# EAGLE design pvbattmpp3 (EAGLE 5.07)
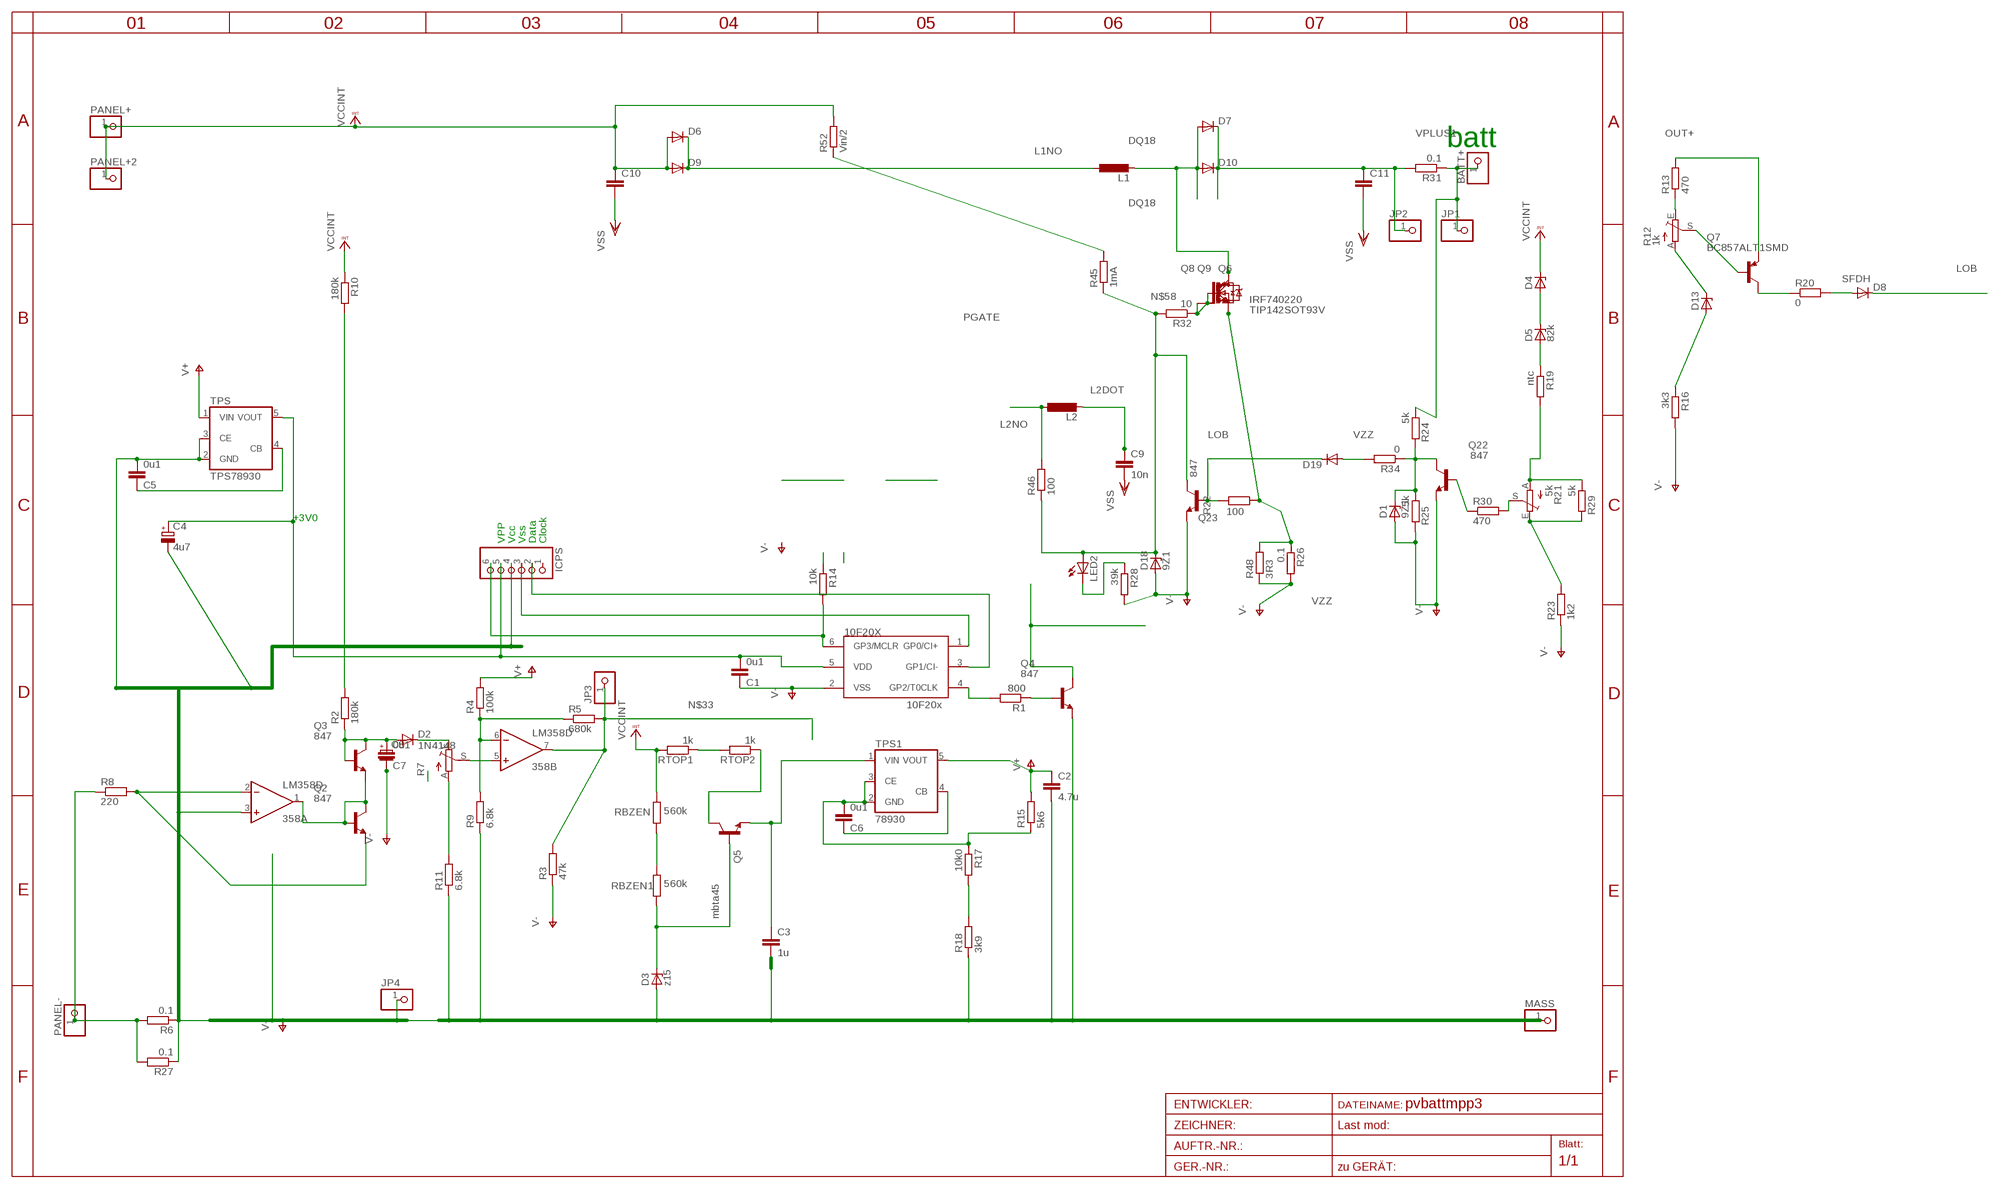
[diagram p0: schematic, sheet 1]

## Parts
10F20X  10F20x  PIC10F204OT  [SOT23-6]
358  LM358D  [SO08]
BATT+  PINHD-1X12MM3  [1X2MM3]
C1  0u1  C-EUC1206  [C1206]
C2  4.7u  C-EUC1206  [C1206]
C3  1u  C-EUC1206  [C1206]
C4  4u7  CPOL-EUSMCA  [SMC_A]
C5  0u1  C-EUC0805  [C0805]
C6  0u1  C-EUC0805  [C0805]
C7  0u1  C-EUC1608  [C1608]
C8  CPOL-EUSMCA  [SMC_A]
C9  10n  C-EUC0805  [C0805]
C10  C-EU075-052X106  [C075-052X106]
C11  C-EU075-052X106  [C075-052X106]
D1  9Z1  ZENER-DIODESOD80C  [SOD80C]
D2  1N4148  DIODE-SOD80C  [SOD80C]
D3  z15  ZENER-DIODESOD80C  [SOD80C]
D4  ZENER-DIODESOD80C  [SOD80C]
D5  82k  ZENER-DIODESOD80C  [SOD80C]
D6  DIODE-SMC  [SMC]
D7  DIODE-SMC  [SMC]
D8  DIODE-MINIMELF  [MINIMELF]
D9  DIODE-SMC  [SMC]
D10  DIODE-SMC  [SMC]
D13  ZENER-DIODESOD80C  [SOD80C]
D18  9Z1  ZENER-DIODESOD80C  [SOD80C]
D19  DIODE-MINIMELF  [MINIMELF]
ICPS  PINHD-1X6  [1X06BOX]
JP1  PINHD-1X11MM6  [1X1MM8]
JP2  PINHD-1X11MM6  [1X1MM8]
JP3  PINHD-1X11MM6  [1X1MM8]
JP4  PINHD-1X11MM6  [1X1MM8]
L1  L-EUOPEN6  [OPEN6_3]
L2  L-EUOPEN6  [OPEN6_3]
LED2  LEDCHIPLED_1206  [CHIPLED_1206]
MASS  PINHD-1X12MM3  [1X2MM3]
PANEL+  PINHD-1X11MM6  [1X1MM8]
PANEL+2  PINHD-1X12MM3  [1X2MM3]
PANEL-  PINHD-1X12MM3  [1X2MM3]
Q2  847  BC847ALT1SMD  [SOT23]
Q3  847  BC847ALT1SMD  [SOT23]
Q4  847  BC847ALT1SMD  [SOT23]
Q5  mbta45  BC847ALT1SMD  [SOT23]
Q6  IRF740220  [TO220BV]
Q7  BC857ALT1SMD  [SOT23-BEC]
Q8  IRG4BC15UD-S  [D2PACK]
Q9  TIP142SOT93V  [SOT93V]
Q22  847  BC847ASMD  [SOT23]
Q23  847  BC847ASMD  [SOT23]
R1  800  R-EU_R0805  [R0805]
R2  180k  R-EU_0207/15  [0207/15]
R3  47k  R-EU_R0805  [R0805]
R4  100k  R-EU_R1206  [R1206]
R5  680k  R-EU_R0805  [R0805]
R6  0.1  R-EU_0207/10  [0207/10]
R7  TRIM_EU-S64W  [S64W]
R8  220  R-EU_R0805  [R0805]
R9  6.8k  R-EU_R1206  [R1206]
R10  180k  R-EU_R1206  [R1206]
R11  6.8k  R-EU_R0805  [R0805]
R12  1k  TRIM_EU-S64W  [S64W]
R13  470  R-EU_R0805  [R0805]
R14  10k  R-EU_R0805  [R0805]
R15  5k6  R-EU_R0805  [R0805]
R16  3k3  R-EU_R0805  [R0805]
R17  10k0  R-EU_R0805  [R0805]
R18  3k9  R-EU_R0805  [R0805]
R19  ntc  R-EU_0204/5  [0204/5]
R20  0  R-EU_R0805  [R0805]
R21  5k  TRIM_EU-S64W  [S64W]
R22  100  R-EU_R1206  [R1206]
R23  1k2  R-EU_R0805  [R0805]
R24  5k  R-EU_R1206  [R1206]
R25  5k  R-EU_R0805  [R0805]
R26  0.1  R-EU_R3216  [R3216]
R27  0.1  R-EU_R3216  [R3216]
R28  39k  R-EU_R0805  [R0805]
R29  5k  R-EU_R0805  [R0805]
R30  470  R-EU_R0805  [R0805]
R31  0.1  R-EU_R1210  [R1210]
R32  10  R-EU_R0805  [R0805]
R34  0  R-EU_R0805  [R0805]
R45  1mA  R-EU_R0805  [R0805]
R46  100  R-EU_R0805  [R0805]
R48  3R3  R-EU_0207/10  [0207/10]
R52  Vin/2  R-EU_R1206  [R1206]
RBZEN  560k  R-EU_R1206  [R1206]
RBZEN1  560k  R-EU_R1206  [R1206]
RTOP1  1k  R-EU_R1206  [R1206]
RTOP2  1k  R-EU_R1206  [R1206]
TPS  TPS78930  TPS78930SOT23-5  [SOT25]
TPS1  78930  TPS78930SOT23-5  [SOT25]

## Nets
CB: D3.C Q5.1(B) RBZEN1.2
DQ18: D7.A D10.A L1.2 Q6.D Q8.2(C) Q9.C
FB: 358.2(A:-IN) Q2.2(E) R8.2
GND1: C6.1 TPS1.4(CB)
IN-: PANEL-.1 R6.2 R8.1 R27.2
L1NO: D6.C D9.C L1.1
L2DOT: C9.1 L2.2
L2NO: L2.1 R46.2
LOB: D8.C D19.C Q4.3(C) Q23.1(B) R22.2
N$1: Q4.1(B) R1.1
N$2: R7.A R11.2
N$4: 10F20X.1(GP0/CI+) ICPS.3
N$5: 10F20X.4(GP2/T0CLK) R1.2
N$6: R2.2 R10.2
N$7: 358.1(A:OUT) Q2.1(B) Q2.3(C) Q3.2(E)
N$8: 10F20X.3(GP1/CI-) ICPS.2
N$9: 10F20X.5(VDD) C1.2 C4.+ ICPS.5 TPS.5(VOUT)
N$10: Q22.1(B) R30.1
N$11: C5.1 TPS.4(CB)
N$12: C7.2 C8.+ D2.A Q3.1(B) Q3.3(C) R2.1
N$13: D2.C R7.E
N$15: 358.5(B:+IN) R7.S
N$16: Q5.3(C) RTOP2.1
N$17: 358.6(B:-IN) R4.1 R5.1 R9.2
N$18: D13.A R16.1
N$19: RBZEN1.1 RBZEN.2
N$20: R14.1
N$21: LED2.C R28.1
N$22: D5.A R19.1
N$26: Q7.B R12.S
N$28: R17.2 R18.2
N$29: RTOP1.1 RTOP2.2
N$30: D4.A D5.C
N$32: R19.2 R21.A R29.1
N$33: 358.7(B:OUT) JP3.1 R3.2 R5.2
N$34: R21.E R23.2 R29.2
N$35: R45.2 R52.1
N$37: R12.E R13.1
N$38: D13.C R12.A
N$58: Q6.G Q8.1(G) Q9.B R32.1
N$71: D1.C Q22.3(C) R24.2 R25.1 R34.1
OUT+: BATT+.1 JP1.1 Q7.E R13.2 R24.1 R31.1
PGATE: D18.C LED2.A Q23.3(C) R32.2 R45.1 R46.1
PIR: 10F20X.6(GP3/MCLR) ICPS.6 R14.2
PRB1: R21.S R30.2
SDFGKSD: Q7.C R20.1
SFDH: D8.A R20.2
SFET1: Q6.S Q8.3(E) Q9.E R22.1 R26.1 R48.2
V15: C3.1 Q5.2(E) TPS1.1(VIN)
V+: C2.1 R4.2 R15.2 TPS1.5(VOUT) TPS.1(VIN)
V-: 10F20X.2(VSS) 358.3(A:+IN) C1.1 C2.2 C3.2 C4.- C5.2 C7.1 C8.- C9.2 C10.2 C11.2 D1.A D3.A D18.A ICPS.4 JP4.1 MASS.1 Q4.2(E) Q22.2(E) Q23.2(E) R3.1 R6.1 R9.1 R11.1 R16.2 R18.1 R23.1 R25.2 R26.2 R27.1 R28.2 R48.1 TPS.2(GND) TPS.3(CE) ; supply symbol labelled VSS
VCCINT: C10.1 D4.C D6.A D9.A PANEL+2.1 PANEL+.1 R10.1 R52.2 RBZEN.1 RTOP1.2
VPLUS1: C11.1 D7.C D10.C JP2.1 R31.2
VZZ: D19.A R34.2
X: C6.2 R15.1 R17.1 TPS1.2(GND) TPS1.3(CE)
Unconnected: ICPS.1

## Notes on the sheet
- batt
- +3V0
- VPP | Vcc | Vss | Data | Clock

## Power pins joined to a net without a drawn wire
V+: 358.8(P:V+)
V-: 358.4(P:V-)

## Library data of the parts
10F20X = microchip-3:PIC10F2*: uPC nW 0,25/0,5k Program Flash memory Comparator
358 = linear:LM358: OP AMP also LM158; LM258; LM2904 Source: http://cache.national.com/ds/LM/LM158.pdf
BATT+ JP1-JP4 MASS PANEL+ PANEL+2 PANEL- = pinhead:PINHD-1X1: PIN HEADER
C1-C3 C5-C7 C9-C11 = rcl:C-EU: CAPACITOR, European symbol
C4 = rcl(2):CPOL-EU: POLARIZED CAPACITOR, European symbol
C8 = rcl:CPOL-EU: POLARIZED CAPACITOR, European symbol
D1 D3-D5 D13 D18 = diode:ZENER-DIODE: Z-Diode
D2 D6-D10 D19 = diode:DIODE-: DIODE
ICPS = pinhead:PINHD-1X6: PIN HEADER
L1 L2 = rcl:L-EU: INDUCTOR, European symbol
LED2 = led:LED: LED
Q2-Q5 Q22 Q23 = transistor-npn:BC847*: NPN Transistor
Q6 = transistor-power:IRF740: N-CHANNEL MOS FET
Q7 = transistor-pnp:BC857*: PNP Transistror
Q8 = transistor-power:IRG4BC15UD-: INSULATED GATE BIPOLAR TRANSISTOR WITH ULTRAFAST SOFT RECOVERY DIODE
Q9 = transistor-power:TIP142: NPN DARLINGTON TRANSISTOR
R1-R6 R8-R11 R13-R20 R22-R31 R34 RBZEN RBZEN1 RTOP1 RTOP2 = rcl:R-EU_: RESISTOR, European symbol
R7 R12 R21 = pot:TRIM_EU-: POTENTIOMETER
R32 R45 R46 R48 R52 = rcl-2:R-EU_: RESISTOR, European symbol
TPS TPS1 = v-reg:TPS78930

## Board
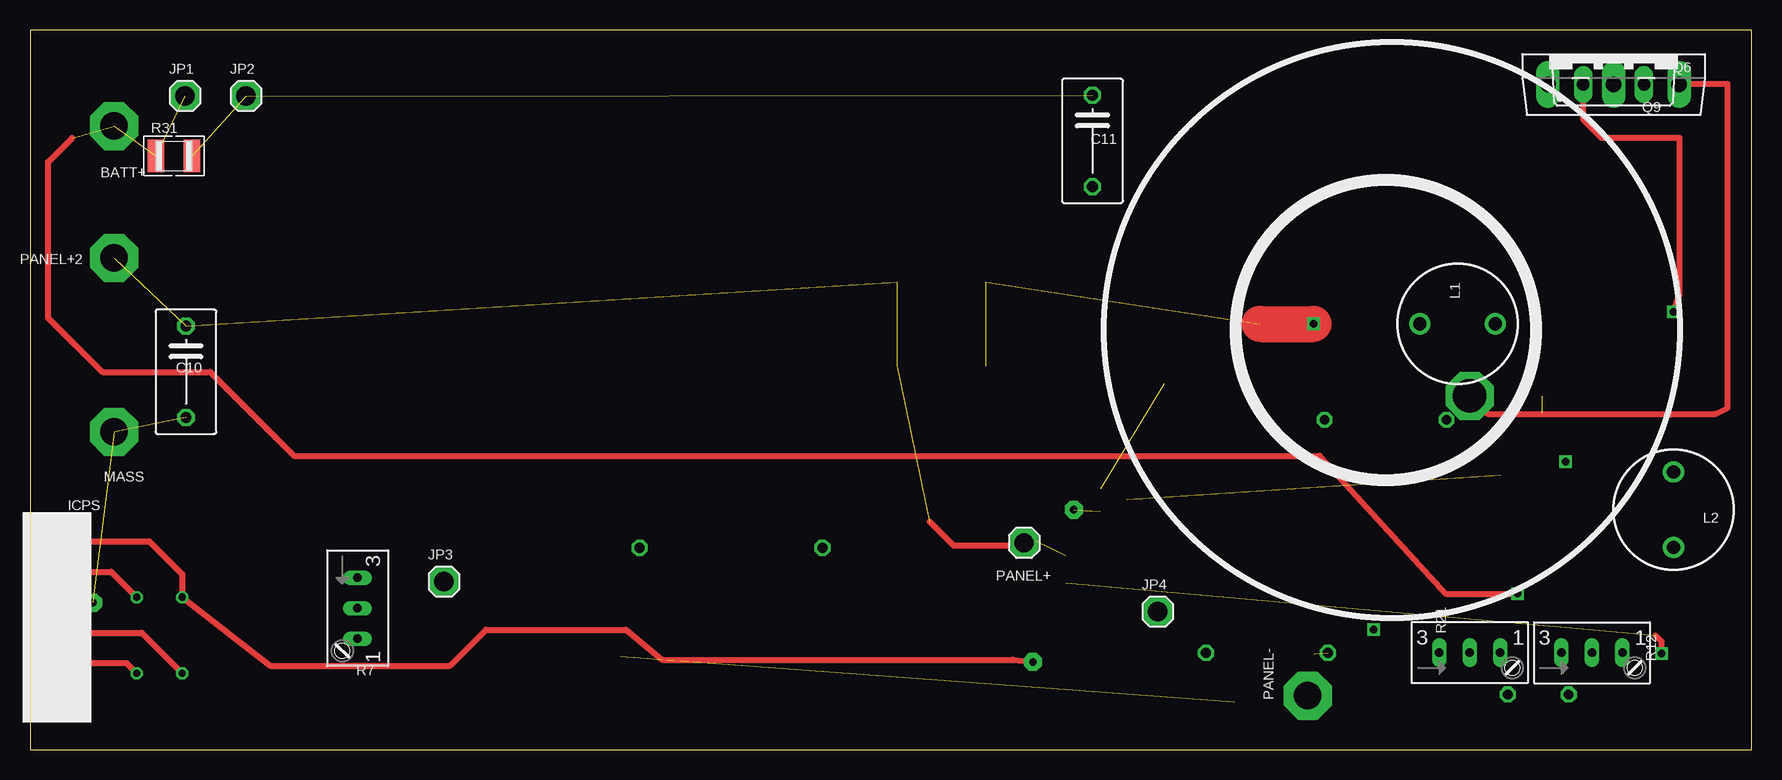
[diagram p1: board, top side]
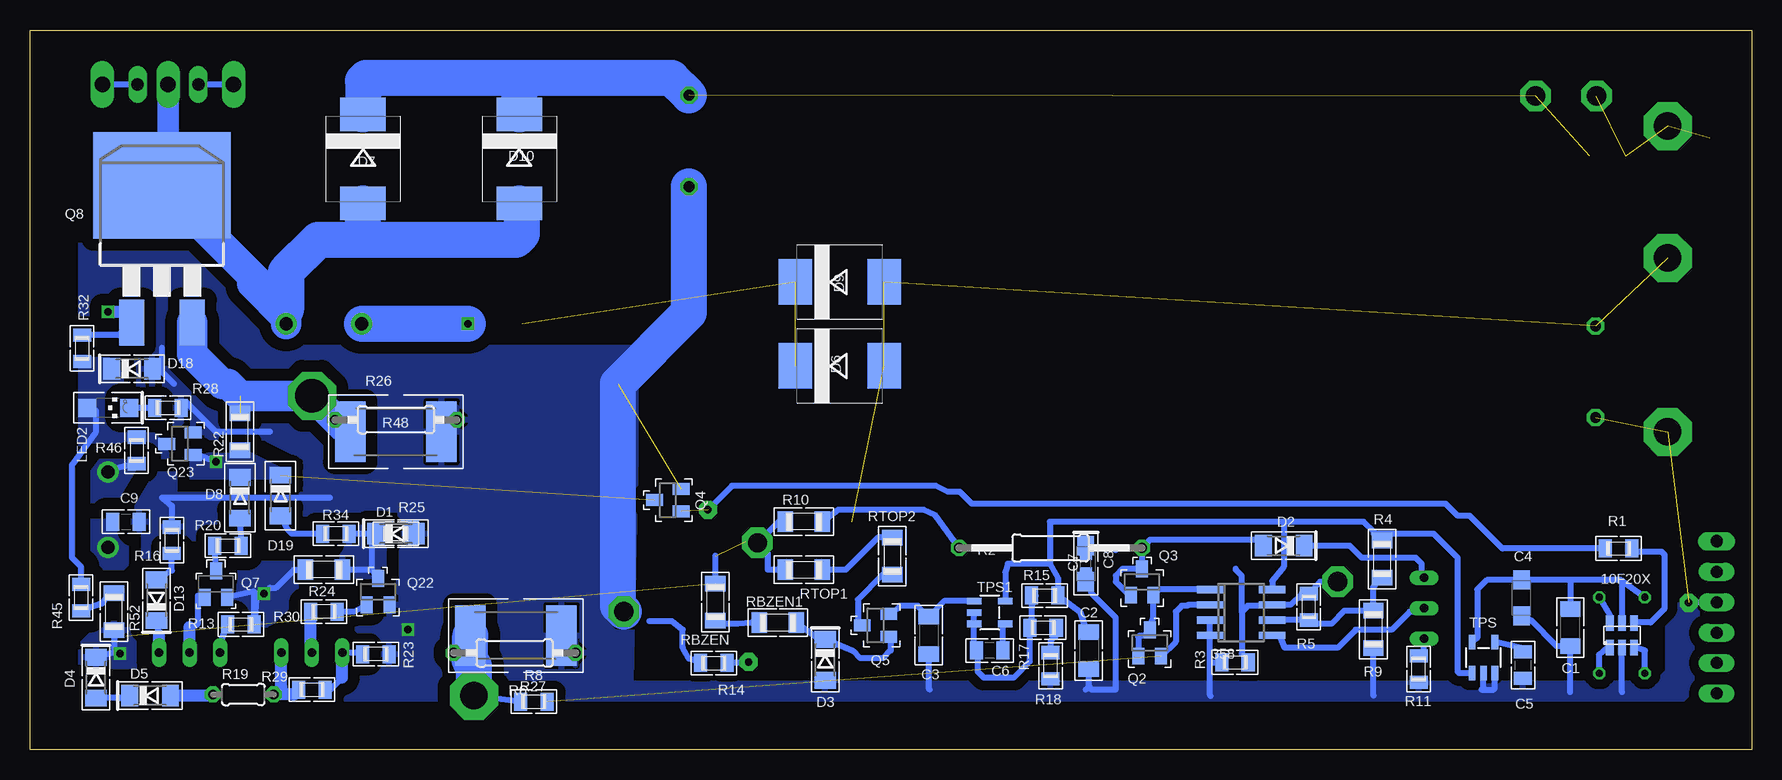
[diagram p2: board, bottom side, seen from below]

Size 143.5 x 60 mm. Coordinates in mm from the lower left corner, seen from the top.
Outline: 0,0 143.5,0 143.5,60 0,60 0,0
Copper layers (1*16): Top 0.035mm / dielectric 1.5mm / Bottom 0.035mm
Design rules "default *": minimum track width 10mil, minimum drill 24mil, track to track 8mil, track to pad 8mil, pad to pad 8mil, via to via 8mil, smd to smd 8mil, copper to edge 4mm, drill to drill 8mil, minimum pad ring 10mil, minimum via ring 8mil, stop-mask expansion 4mil, vias tented up to drill 0mil, thermal gap 10mil

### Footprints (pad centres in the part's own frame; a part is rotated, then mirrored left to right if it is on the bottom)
SOT23-6 = smd 0.635 x 1.27: 1 -1.016,-1.016; 2 0,-1.016; 3 1.016,-1.016; 4 1.016,1.016; 5 0,1.016; 6 -1.016,1.016
SO08 = smd 0.6 x 2.2: 1 -1.905,-2.6; 2 -0.635,-2.6; 3 0.635,-2.6; 4 1.905,-2.6; 5 1.905,2.6; 6 0.635,2.6; 7 -0.635,2.6; 8 -1.905,2.6
1X2MM3 = drill 2.3 pad 4 octagon: 1 0,0
C1206 = smd 1.3 x 1.7: 1 -1.55,0; 2 1.55,0
SMC_A = smd 1.6 x 1.4: + -1.5,0; - 1.5,0
C0805 = smd 1.1 x 1.5: 1 -1.1,0; 2 1.1,0
C1608 = smd 1.1 x 1: 1 -0.85,0; 2 0.85,0
C075-052X106 = drill 0.914 octagon: 1 -3.81,0; 2 3.81,0
SOD80C = smd 1.4 x 1.8: A 1.7,0; C -1.7,0
SMC = smd 2.8 x 3.8: A 3.7,0; C -3.7,0
MINIMELF = smd 1.4 x 1.8: A 1.7,0; C -1.7,0
1X06BOX = drill 1 long: 1 -6.35,0; 2 -3.81,0; 3 -1.27,0; 4 1.27,0; 5 3.81,0 | drill 1.016 long: 6 6.35,0
1X1MM8 = drill 1.6 pad 2.54 octagon: 1 0,0
OPEN6_3 = drill 1.1 pad 1.778 round: 1 -3.15,0; 2 3.15,0
CHIPLED_1206 = smd 1.5 x 1.5: A 0,-1.75; C 0,1.75
SOT23 = smd 1 x 1.4: 1 -0.95,-1.1; 2 0.95,-1.1; 3 0,1.1
TO220BV = drill 1.016 long: D 0,-2.54; G -2.54,-2.54; S 2.54,-2.54
SOT23-BEC = smd 1 x 1.4: B -0.95,-1.1; C 0,1.1; E 0.95,-1.1
D2PACK = smd 2.083 x 3.81: 1 -2.54,-8.89; 3 2.54,-8.89 | smd 11.43 x 8.89: 2 0,2.54
SOT93V = drill 1.3 pad 1.676 long: B -5.461,-2.54; C 0,-2.54; E 5.461,-2.54
R0805 = smd 1.1 x 1.5: 1 -1.1,0; 2 1.1,0
0207/15 = drill 0.813 octagon: 1 -7.62,0; 2 7.62,0
R1206 = smd 1.3 x 1.7: 1 -1.55,0; 2 1.55,0
0207/10 = drill 0.813 octagon: 1 -5.08,0; 2 5.08,0
S64W = drill 0.7 long: A 2.54,1.27; E -2.54,1.27; S 0,1.27
0204/5 = drill 0.813 octagon: 1 -2.54,0; 2 2.54,0
R3216 = smd 2.54 x 5.08: 1 -3.81,0; 2 3.81,0
R1210 = smd 1.4 x 2.7: 1 -1.5,0; 2 1.5,0
SOT25 = smd 0.55 x 1.2: 1 -0.95,-1.3; 2 0,-1.3; 3 0.95,-1.3; 4 0.95,1.3; 5 -0.95,1.3

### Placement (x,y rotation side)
10F20X  10.79,9.53 0 bottom
358  42.55,11.43 270 bottom
BATT+  7,52 0 top
C1  15.11,10.16 90 bottom
C2  55.24,8.26 270 bottom
C3  68.58,9.53 270 bottom
C4  19.18,12.63 270 bottom
C5  19.05,7.04 270 bottom
C6  63.5,8.26 180 bottom
C7  55.5,15.5 90 bottom
C8  55.5,15.5 270 bottom
C9  135.5,19 0 bottom
C10  13,31.5 270 top
C11  88.56,50.75 270 top
D1  113,18 0 bottom
D2  39,17 180 bottom
D3  77.22,7.48 270 bottom
D4  138,6 270 bottom
D5  133.5,4.5 0 bottom
D6  76,32 0 bottom
D7  115.73,49.25 270 bottom
D8  126,21 270 bottom
D9  76,39 0 bottom
D10  102.71,49.25 270 bottom
D13  132.96,12.46 90 bottom
D18  135,31.75 0 bottom
D19  122.62,21.17 270 bottom
ICPS  2.9,11.02 90 top
JP1  12.92,54.5 0 top
JP2  18,54.5 0 top
JP3  34.5,14 0 top
JP4  94,11.5 0 top
L1  119,35.5 0 top
L2  137,20 270 top
LED2  137,28.5 270 bottom
MASS  7,26.5 0 top
PANEL+  82.86,17.24 0 top
PANEL+2  7,41 0 top
PANEL-  106.5,4.5 90 top
Q2  50.16,8.89 0 bottom
Q3  50.8,13.97 0 bottom
Q4  90.33,20.8 90 bottom
Q5  73.03,10.35 90 bottom
Q6  132,58 0 top
Q7  128,13.8 0 bottom
Q8  132.5,44.5 0 bottom
Q9  132,58 0 top
Q22  114.49,13.16 0 bottom
Q23  131,25.5 90 bottom
R1  11.08,16.77 0 bottom
R2  58.44,16.81 180 bottom
R3  43.05,7.27 0 bottom
R4  30.8,15.88 90 bottom
R5  36.9,11.9 90 bottom
R6  103.11,8.05 180 bottom
R7  26.04,11.79 270 top
R8  101.5,4 0 bottom
R9  31.52,10.03 90 bottom
R10  79,19 0 bottom
R11  27.75,6.71 90 bottom
R12  130.21,6.8 0 top
R13  125.92,10.44 0 bottom
R14  86.5,7.21 0 bottom
R15  58.92,12.84 0 bottom
R16  131.68,17.45 90 bottom
R17  59.05,10.16 0 bottom
R18  58.42,6.99 90 bottom
R19  125.72,4.59 0 bottom
R20  127,17 0 bottom
R21  120.01,6.82 0 top
R22  126,26.5 270 bottom
R23  114.66,7.96 180 bottom
R24  119,15 0 bottom
R25  113,18 0 bottom
R26  113,26.5 0 bottom
R27  103,9.5 180 bottom
R28  132,28.5 0 bottom
R29  120,5 0 bottom
R30  119,11.5 180 bottom
R31  12,49.5 0 top
R32  139.16,33.45 270 bottom
R34  118,18 180 bottom
R45  139.25,12.67 270 bottom
R46  134.61,24.94 270 bottom
R48  113,27.5 180 bottom
R52  136.5,11.5 270 bottom
RBZEN  86.36,12.29 270 bottom
RBZEN1  81.16,10.57 0 bottom
RTOP1  79,15 180 bottom
RTOP2  71.62,16.12 90 bottom
TPS  22.35,7.67 0 bottom
TPS1  63.5,11.43 270 bottom

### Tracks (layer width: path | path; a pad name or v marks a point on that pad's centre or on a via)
CB
  Bottom 0.5: Q5.1 71.75,9.23 71.75,8.26 72.39,7.62 74.3,7.62 74.85,8.18 D3.C 77.72,9.18 RBZEN1.2
DQ18
  Bottom 1.778: 132,47.54 Q9.C
  Bottom 2.54: 122.15,36 L1.2 | 122.15,36 122.15,36.65 132,46.5 132,46.54 Q8.2 132,47.54 | 122.15,36 125,38.85
  Bottom 3: 122.15,36.65 122.15,39.85 119.5,42.5 116,42.5 | 116,42.5 103,42.5 102.5,43 102.5,45.34 D10.A | D7.A 115.73,42.77 116,42.5
FB  (1 unrouted)
  Bottom 0.5: 358.2 46.94,12.06 47,12 47.5,12 48,11.5 48,9 Q2.2
GND1
  Bottom 0.5: C6.1 62.4,10.28 TPS1.4
IN-  (1 unrouted)
  Bottom 0.5: R8.1 PANEL-.1
  Bottom 3: PANEL-.1 106.5,7 106.81,7.31 | 106.81,7.31 107,8 | 106.81,7.31 R27.2
L1NO  (via drill 0.6)  (2 unrouted)
  Top 3: 102.5,35.5 v107,35.5
  Bottom 3: v107,35.5 L1.1
L2DOT
  pour Bottom (isolate 1.27, no thermals): 137,19 138.5,19 138.5,15 136,15 135.5,15.5 135.5,17.5 136,18
L2NO
  Bottom 0.5: R46.2 136.69,23.34 L2.1
  pour Bottom (isolate 1.27, no thermals): 134.5,24 138.5,24 139,23.5 139,21 138.5,20.5 136.5,20.5 136,21.5
LOB  (via drill 0.6)  (1 unrouted)
  Bottom 0.5: Q23.1 129.55,24.55 v128,24
  pour Bottom (isolate 1.27, no thermals): 122,22.5 122,23 125,24.5 128,24.5 130,25 130,22.5
N$1  (via drill 0.6 pad 1.5)  (1 unrouted)
  Bottom 0.5: R1.1 20.77,16.77 23.5,19.5 24.5,19.5 25.5,20.5 65,20.5 66,21.5 67,21.5 68,22 85,22 v87,20
N$2
  Bottom 0.5: R7.A 27.3,8.26 R11.2
N$4  (via drill 0.6)
  Top 0.5: ICPS.3 9.3,9.75 v12.7,6.35
  Bottom 0.5: v12.7,6.35 12.7,7.9 11.99,8.51 10F20X.1
N$5
  Bottom 0.5: 10F20X.4 9.72,10.6 8.4,10.6 7.24,11.76 7.24,16.24 7.5,16.5 9.71,16.5 R1.2
N$6
  Bottom 0.5: R2.2 68.06,19.56 69,20 76.14,20 R10.2
N$7
  Bottom 0.5: 358.1 49.38,13.34 Q3.2 49.9,12.42 49.9,10.9 50.16,10.34 Q2.3 50.66,9.5 51,9.5 51.12,9.38 Q2.1
N$8  (via drill 0.6)
  Top 0.5: ICPS.2 8.03,7.21 v8.89,6.35
  Bottom 0.5: v8.89,6.35 8.89,8.26 10F20X.3
N$9  (via drill 0.6)
  Top 0.5: ICPS.5 6.76,14.83 v8.89,12.7
  Bottom 0.5: 15.24,14.13 10.86,14.13 10.75,14.02 | 15.24,14.13 C4.+ 22.06,14.13 22.86,13.34 22.86,9.3 TPS.5 | v8.89,12.7 10.7,13.97 10.75,14.02 | 10F20X.5 10.79,13.97 10.75,14.02 | C1.2 15.11,14 15.24,14.13
N$10
  Bottom 0.5: R30.1 116.5,11.5 Q22.1
N$11
  Bottom 0.5: TPS.4 19.25,8.47 C5.1
N$12
  Bottom 0.5: D2.A 41,17.5 50.13,17.5 R2.1 | R2.1 52.82,16.78 53.12,16.73 | Q3.1 51.87,12.87 53,14 53,14.5 52.43,15.07 Q3.3 50.82,15.09 R2.1 | 53.12,16.73 53,16.62 | C7.2 C8.+ 55.23,16.73 53.12,16.73
N$13
  Bottom 0.5: D2.C 33.49,16.99 32.5,16 28,16 27.5,15.5 27.5,14.03 R7.E
N$15
  Bottom 0.5: 358.5 39.33,9.53 38.9,8.5 34.5,8.5 33,10 30,10 28.5,11.5 27.59,11.5 R7.S
N$16
  Bottom 0.5: RTOP2.1 72.43,14.57 74.5,12.5 74.5,10.73 Q5.3
N$17
  Bottom 0.5: R4.1 31.52,13.55 R9.2 33.92,11.57 35,10.5 36.59,10.5 R5.1 37.91,10.79 358.6
N$18
  Bottom 0.5: R16.1 131.68,14.94 D13.A
N$19
  Bottom 0.5: RBZEN1.1 83.37,10.57 84.5,10.5 85.61,10.5 RBZEN.2
N$20
  Bottom 0.5: R14.1 88.59,7.59 89.1,8.5 89.1,10 90,10.7 91.87,10.7
N$21
  Bottom 0.5: R28.1 LED2.C
N$22
  Bottom 0.5: R19.1 128.35,4.5
  Bottom 1: 128.35,4.5 D5.A
N$26
  Bottom 0.5: 130.21,10.21 129.5,10.5 129.5,12.85 Q7.B
  Bottom 1: R12.S 130.21,10.21
N$28
  Bottom 0.5: R18.2 58.42,9.08 58,9.5 58,10.12 R17.2
N$29
  Bottom 0.5: RTOP1.1 75.52,14.98 72.83,17.67 RTOP2.2
N$30
  Bottom 0.5: D4.A 136,4.3 D5.C
N$32
  Bottom 0.5: R29.1 121.51,4.59 | R19.2 122.55,5.22
  Bottom 1: 121.51,4.59 R19.2 | 122.55,5.22 R21.A
N$33
  Bottom 0.5: R3.2 42.05,7.54 42.5,8 42.5,11.5 | 42.5,11.5 42,12 40.01,12 358.7 38.44,12.06 37.5,13 R5.2 35.95,14 JP3.1 | 42.5,11.5 42.5,14.5 43,15 43,15.1
N$34
  Bottom 0.5: R29.2 118.5,5 117.5,6 | 117.5,8.06 R21.E 116.12,8.09 R23.2
  Bottom 1: 117.5,6 117.5,8.06
N$35
  Bottom 0.5: R52.1 136.5,13 137,13 137.5,12.18 R45.2
N$37
  Bottom 0.5: R13.1 127.76,8.48 R12.E
N$38
  Bottom 0.5: 132.75,9.55 D13.C
  Bottom 1: R12.A 132.75,9.55
N$58  (via drill 0.6)
  Top 0.5: Q6.G 129.46,52.54 131,51 137.5,51 137.5,38 v137,36.5
  Bottom 0.5: 135.93,36.5 Q8.1 136.09,34.55 R32.1 | Q6.G Q9.B
  Bottom 1: 135.93,36.5 v137,36.5
N$71
  Bottom 0.5: R34.1 D1.C 114.99,17.71 114.99,15 | Q22.3 114.99,15 | 114.99,15 R24.2
  pour Bottom (isolate 1.27, rank 2): 114,18.5 117,18.5 117.5,18 117.5,14.5 114.5,14.5 114,15
OUT+  (via drill 0.6)  (3 unrouted)
  Top 0.5: v124,13 118,13 107.5,24.5 22,24.5 15,31.5 6,31.5 1.5,36 1.5,49 3.5,51
  Bottom 0.5: R24.1 121.5,15 123,13.5 123.5,13.5 v124,13 124.62,13 R13.2 124.83,13.18 Q7.E
  pour Bottom (isolate 1.27, rank 2): 121,15.5 126,15.5 127,14.5 127,11 126,10 124,10 121.5,12.5
PGATE
  Bottom 0.5: LED2.A 138,28.25 138,26.5 140,23.75 140,16 139.25,15.25 R45.1
  pour Bottom (isolate 1.27, rank 2, no thermals): 136.5,32.5 140.5,32.5 140.5,24.5 132,24.5 132.5,25.5 134.5,27.5 136,31
PIR  (via drill 0.6, 0.6 pad 1.5)
  Top 0.5: v83.6,7.3 81.92,7.48 52.67,7.48 49.67,10 38,10 35,7 20.04,7 v12.7,12.7 12.7,14.61 9.94,17.37 ICPS.6
  Bottom 0.5: 10F20X.6 11.81,11.18 v12.7,12.7 | R14.2 84.58,7.21 v83.6,7.3
PRB1
  Bottom 0.5: R21.S 120.1,8.18
  Bottom 1: 120.1,8.18 R30.2
SDFGKSD
  Bottom 0.5: Q7.C R20.1
SFDH
  Bottom 0.5: R20.2 125.9,17.7 D8.A
SFET1  (via drill 2.8 pad 4)  (1 unrouted)
  Top 0.5: Q9.E 141.46,55.46 141.5,55.5 141.5,28.5 140.5,28 121.5,28 v120,29.5
  Bottom 0.5: Q9.E Q6.S | R48.2 118.08,27.58 118.5,28
  Bottom 2.54: Q8.3 129.96,32.96 127.5,30.5 127,30.5 126,29.5 v120,29.5 119.75,29.25 118.5,28 117.5,27 117.31,27 R26.1
V15
  Bottom 0.5: TPS1.1 67.28,12.38 C3.1 69.5,12 71,12 71.7,11.3 Q5.2
V+
  Bottom 0.5: TPS.1 24.38,6.38 24.5,6.5 24.5,16 26.5,18 31.5,18 31.5,18.18 | 31.5,18.18 R4.2 | 39,19 32.32,19 31.5,18.18 | 39,19 58.5,19 58.5,15.5 | C2.1 55.24,9.74 55.5,10 56,11.5 R15.2 57.82,14.32 58.5,15.5 | TPS1.5 62.2,14.8 62,15.5 58.5,15.5 | 358.8 39.95,14.05 39,15.25 39,19
V-  (via drill 0.6, 0.6 pad 1.5)  (3 unrouted)
  Top 0.5: ICPS.4 5.21,12.29 v5.25,12.25
  Bottom 0.5: 15.11,4.81 C1.1 16.23,8.62 18.41,10.79 18.84,10.79 C4.- | 10.79,4.81 10F20X.2 | 45.15,7.27 45.15,4.5 45.09,4.45 | 358.3 358.4 45.15,7.27 | v5.25,12.25 4.54,12.25 ICPS.4 | R9.1 31.52,4.53 31.5,4.5 | C3.2 68.58,5.08 68.5,5 | 55.24,5.25 C2.2 | 55.24,5.25 55.5,5 | TPS.3 21.4,5.1 21.5,5 22.5,5 22.35,5.15 TPS.2 | 55.24,5.25 54.99,5 53,5 53,11 55,13 C7.1 C8.- | 45.15,7.27 R3.1 | R16.2 131.68,20.32 132.5,21 118.5,21 | 123.5,26.5 128,26.5 130.5,29 R28.2 | D18.A 132.75,31.75 132.5,31.5 | 131.5,30.5 132.5,31.5 | 132.5,31.5 132.5,33.5
  Bottom 3: C11.2 88.56,36.44 94.5,30.5 94.5,12 JP4.1
  other vias: 112,10
  pour Bottom (isolate 0.813): 1.5,12.5 6.5,12 7,11.5 7,6.5 8,5.5 95.5,5.5 96.5,4.5 96.5,3.5 95,2 8,2 5,5 5,9
  pour Bottom (isolate 1, rank 3): 121,33.5 142,56.5 142,3 107,2.5 107,2 93.5,2 93,24.5 93,33.5
VCCINT  (via drill 0.6)  (6 unrouted)
  Top 0.5: 75,19 77,17 82.62,17 PANEL+.1 | v136,8 136,9 135.5,9.5
  Bottom 0.5: PANEL+.1 83.86,17.34 | RBZEN.1 86.36,16.16 | PANEL+.1 82,16.38 82,15 RTOP1.2 | PANEL+.1 81.1,19 R10.1 | D4.C 136.2,8.2 v136,8 136.5,8.5 R52.2
  pour Bottom (isolate 1.27, rank 2): 133.5,10.5 137.5,10.5 140,8 140,7.5 139.5,7 134,7 133.5,7.5
VPLUS1  (2 unrouted)
  Bottom 3: D7.C 115.73,55.77 115.5,56 102.5,56 | 102.5,56 90,56 C11.1 | D10.C 102.71,55.79 102.5,56
VZZ
  Bottom 0.5: D19.A 122.1,18.45 121.65,18 R34.2
X
  Bottom 0.5: R15.1 59.66,12.84 60,12 60,11.01 R17.1 60.16,7.34 61.5,6 64,6 64.5,6.5 64.5,8.15 C6.2 64.8,8.46 TPS1.3 TPS1.2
